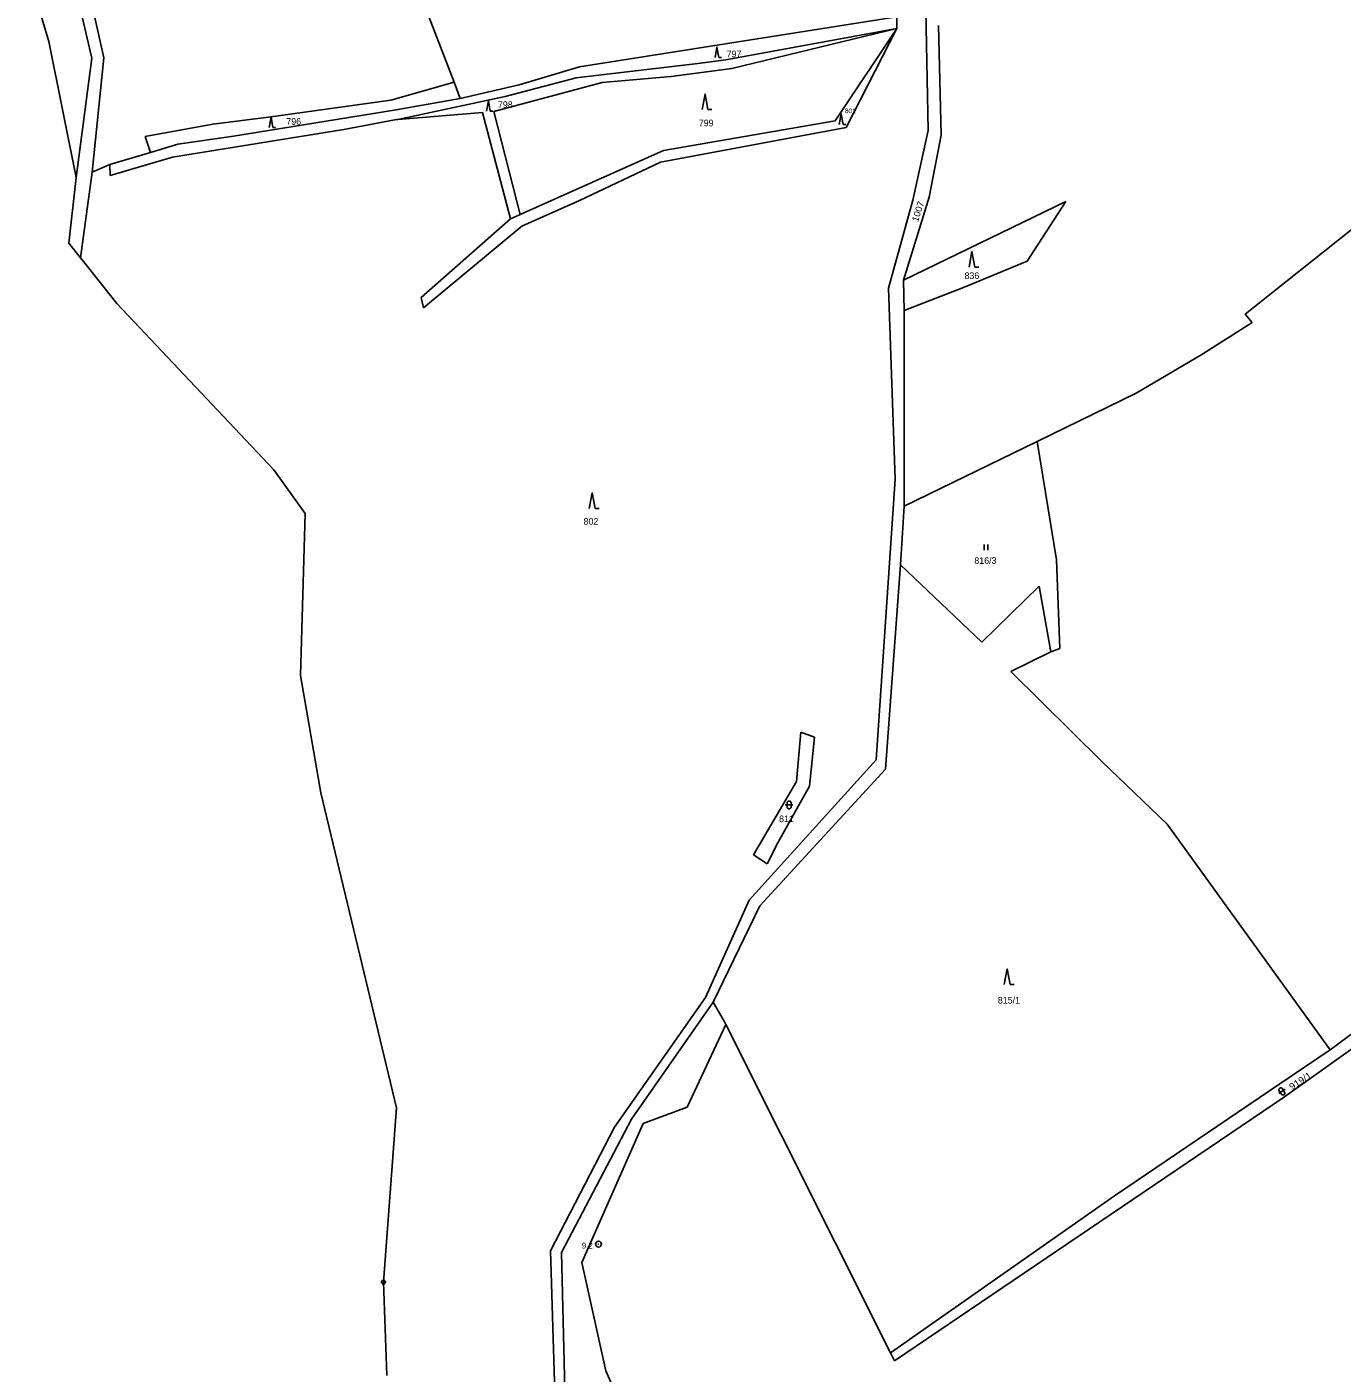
# Model space of a CAD drawing. Extents: x -744132 to -742433, y -984679 to -982287.
# Drawn here: x -744088.1 to -743750.5, y -983360 to -983014.5 of the extents above; entities that cross this region are included whole.
import ezdxf
from ezdxf.enums import TextEntityAlignment as Align

# ---------------------------------------------------------------- set-up
doc = ezdxf.new("R2010")
doc.units = 0
doc.header["$LTSCALE"] = 0.68
for name, color, linetype, lineweight in [('1', 7, 'Continuous', 25), ('3', 7, 'Continuous', 25), ('8', 7, 'Continuous', 25)]:
    doc.layers.add(name, color=color, linetype=linetype, lineweight=lineweight)
doc.layers.add('2', color=7, linetype='Continuous')

msp = doc.modelspace()

# ---------------------------------------------------------------- linework, layer by layer
at = {"layer": '1'}
for p, q in [((-744068.32, -983022.46), (-744075.46, -982990.35)), ((-744071.39, -983022.53), (-744078.73, -982990.95)), ((-744088.07, -982999.56), (-744082.42, -983018.25)), ((-743988.75, -983001.83), (-743978.43, -983028.72)), ((-743856.71, -983041.1), (-743857.33, -983010.2)), ((-743946.2, -983024.79), (-743864.76, -983011.89)), ((-743864.76, -983011.89), (-743864.74, -983014.91)), ((-743854.03, -983014.11), (-743853.38, -983042.28)), ((-743907.08, -983025.18), (-743864.74, -983014.91)), ((-743880.6, -983038.62), (-743864.74, -983014.91)), ((-743877.79, -983040.3), (-743864.74, -983014.91)), ((-744082.42, -983018.25), (-744075.45, -983053.19)), ((-744071.39, -983022.53), (-744075.45, -983053.19)), ((-744068.32, -983022.46), (-744071.3, -983051.79)), ((-743961.67, -983029.4), (-743946.2, -983024.79)), ((-743947.1, -983027.57), (-743915.85, -983023.86)), ((-743965.31, -983032.34), (-743947.1, -983027.57)), ((-743940.43, -983028.79), (-743922.65, -983027.26)), ((-743922.65, -983027.26), (-743907.08, -983025.18)), ((-743994.69, -983033.33), (-743978.43, -983028.72)), ((-743978.43, -983028.72), (-743976.84, -983032.9)), ((-743976.84, -983032.9), (-743961.67, -983029.4)), ((-743940.43, -983028.79), (-743968.2, -983036.18)), ((-744026.05, -983037.66), (-743994.69, -983033.33)), ((-743976.84, -983032.9), (-743993.28, -983035.82)), ((-743992.82, -983038.24), (-743965.31, -983032.34)), ((-744040.33, -983039.5), (-744026.05, -983037.66)), ((-743993.28, -983035.82), (-744035.03, -983042.53)), ((-743993.21, -983038.29), (-744006.69, -983040.82)), ((-743992.82, -983038.24), (-743993.21, -983038.29)), ((-743971.16, -983036.51), (-743992.82, -983038.24)), ((-743963.92, -983063.75), (-743971.16, -983036.51)), ((-743968.2, -983036.18), (-743961.46, -983062.65)), ((-743924.66, -983046.23), (-743880.6, -983038.62)), ((-744057.72, -983042.67), (-744040.33, -983039.5)), ((-744006.69, -983040.82), (-744050.73, -983047.93)), ((-743925.42, -983049.23), (-743877.79, -983040.3)), ((-743860.62, -983058.97), (-743856.71, -983041.1)), ((-743853.38, -983042.28), (-743856.43, -983058.2)), ((-744056.34, -983046.75), (-744057.72, -983042.67)), ((-744049.31, -983044.58), (-744056.34, -983046.75)), ((-744035.03, -983042.53), (-744049.31, -983044.58)), ((-744066.82, -983049.8), (-744056.34, -983046.75)), ((-744050.73, -983047.93), (-744066.7, -983052.68)), ((-743961.46, -983062.65), (-743924.66, -983046.23)), ((-743946.23, -983059.07), (-743925.42, -983049.23)), ((-744071.3, -983051.79), (-744074.3, -983073.78)), ((-744066.82, -983049.8), (-744071.3, -983051.79)), ((-744066.82, -983049.8), (-744066.7, -983052.68)), ((-744075.45, -983053.19), (-744077.28, -983070.03)), ((-743961.03, -983065.64), (-743946.23, -983059.07)), ((-743866.9, -983081.58), (-743860.62, -983058.97)), ((-743856.43, -983058.2), (-743863.07, -983079.53)), ((-743863.07, -983079.53), (-743821.36, -983059.36)), ((-743821.36, -983059.36), (-743831.27, -983074.64)), ((-743963.92, -983063.75), (-743961.46, -983062.65)), ((-743986.86, -983084), (-743963.92, -983063.75)), ((-743986.28, -983086.57), (-743961.03, -983065.64)), ((-743747.4, -983065.95), (-743775.33, -983088.23)), ((-744077.28, -983070.03), (-744074.3, -983073.78)), ((-744074.3, -983073.78), (-744072.89, -983075.56)), ((-744072.89, -983075.56), (-744064.97, -983085.53)), ((-743831.27, -983074.64), (-743847.68, -983081.43)), ((-743862.92, -983087.27), (-743863.07, -983079.53)), ((-743865.2, -983130.57), (-743866.9, -983081.58)), ((-743847.68, -983081.43), (-743862.92, -983087.27)), ((-744064.97, -983085.53), (-744024.7, -983128.17)), ((-743986.86, -983084), (-743986.28, -983086.57)), ((-743862.92, -983087.27), (-743862.86, -983137.53)), ((-743786.49, -983098.57), (-743773.52, -983090.41)), ((-743773.52, -983090.41), (-743775.33, -983088.23)), ((-743803.29, -983108.52), (-743786.49, -983098.57)), ((-743828.77, -983120.93), (-743803.29, -983108.52)), ((-743862.86, -983137.53), (-743828.77, -983120.93)), ((-743823.78, -983151.26), (-743828.77, -983120.93)), ((-744024.7, -983128.17), (-744016.63, -983139.41)), ((-743870.07, -983202.63), (-743865.2, -983130.57)), ((-743862.86, -983137.53), (-743863.8, -983152.55)), ((-744016.63, -983139.41), (-744017.88, -983180.94)), ((-743863.8, -983152.55), (-743867.67, -983205.06)), ((-743863.8, -983152.55), (-743842.94, -983172.39)), ((-743822.92, -983174.05), (-743823.78, -983151.26)), ((-743842.94, -983172.39), (-743828.24, -983158.03)), ((-743828.24, -983158.03), (-743825.25, -983174.92)), ((-743835.53, -983179.96), (-743825.25, -983174.92)), ((-743825.25, -983174.92), (-743822.92, -983174.05)), ((-743812.18, -983203.03), (-743835.53, -983179.96)), ((-744017.88, -983180.94), (-744012.6, -983211.1)), ((-743890.53, -983208.23), (-743889.37, -983195.5)), ((-743889.37, -983195.5), (-743885.92, -983196.78)), ((-743885.92, -983196.78), (-743887.17, -983209.4)), ((-743902.64, -983238.65), (-743870.07, -983202.63)), ((-743795.41, -983219.1), (-743812.18, -983203.03)), ((-743901.59, -983227.05), (-743890.53, -983208.23)), ((-743867.67, -983205.06), (-743899.93, -983240.12)), ((-744012.6, -983211.1), (-743993.19, -983291.95)), ((-743887.17, -983209.4), (-743895.2, -983223.73)), ((-743753.54, -983277.08), (-743795.41, -983219.1)), ((-743895.2, -983223.73), (-743898.03, -983229.33)), ((-743898.03, -983229.33), (-743901.59, -983227.05)), ((-743902.64, -983238.65), (-743913.9, -983263.64)), ((-743899.93, -983240.12), (-743911.88, -983264.84)), ((-743704.56, -983240.84), (-743753.54, -983277.08)), ((-743913.9, -983263.64), (-743937.21, -983296.92)), ((-743911.88, -983264.84), (-743932.88, -983294.87)), ((-743911.88, -983264.84), (-743908.97, -983269.89)), ((-743765.21, -983289.16), (-743733.29, -983266.29)), ((-743908.97, -983269.89), (-743908.62, -983270.58)), ((-743908.62, -983270.58), (-743918.59, -983291.77)), ((-743908.62, -983270.58), (-743866.41, -983354.8)), ((-743766.49, -983285.81), (-743753.54, -983277.08)), ((-743808.87, -983314.53), (-743766.49, -983285.81)), ((-743865.37, -983356.9), (-743765.21, -983289.16)), ((-743993.19, -983291.95), (-743996.56, -983336.67)), ((-743918.59, -983291.77), (-743929.92, -983295.93)), ((-743937.21, -983296.92), (-743953.68, -983328.65)), ((-743932.88, -983294.87), (-743950.83, -983329.06)), ((-743929.92, -983295.93), (-743945.63, -983331.63)), ((-743866.41, -983354.8), (-743808.87, -983314.53)), ((-743953.68, -983328.65), (-743951.88, -983384.93)), ((-743950.83, -983329.06), (-743948.3, -983432.7)), ((-743945.63, -983331.63), (-743939.5, -983359.44)), ((-743996.56, -983336.67), (-743995.72, -983360.62)), ((-743866.41, -983354.8), (-743865.37, -983356.9)), ((-743939.5, -983359.44), (-743926.31, -983389.16))]:
    msp.add_line(p, q, dxfattribs=at)
msp.add_lwpolyline([(-743915.85, -983023.86), (-743908.66, -983022.98), (-743864.74, -983014.91)], dxfattribs=at)
at = {"layer": '3'}
for p, q in [((-743910.428, -983022.37), (-743909.76, -983022.37)), ((-743969.118, -983036.13), (-743968.45, -983036.13)), ((-743913.25, -983035.74), (-743912.254, -983035.74)), ((-744024.908, -983040.36), (-744024.24, -983040.36)), ((-743878.538, -983039.58), (-743877.87, -983039.58)), ((-743844.73, -983076.15), (-743843.734, -983076.15)), ((-743942.21, -983138.13), (-743941.214, -983138.13)), ((-743842.381, -983148.83), (-743842.381, -983147.33)), ((-743841.38, -983148.83), (-743841.38, -983147.33)), ((-743893.431, -983214.211), (-743891.429, -983214.211)), ((-743892.931, -983213.711), (-743892.931, -983214.712)), ((-743891.929, -983214.712), (-743891.929, -983213.711)), ((-743835.67, -983260.3), (-743834.674, -983260.3)), ((-743766.744, -983288.288), (-743765.064, -983287.197)), ((-743766.596, -983287.595), (-743766.051, -983288.435)), ((-743765.212, -983287.889), (-743765.757, -983287.05))]:
    msp.add_line(p, q, dxfattribs=at)
for points in [[(-743910.428, -983022.37), (-743910.93, -983019.69), (-743911.432, -983022.37)], [(-743913.25, -983035.74), (-743914, -983031.74), (-743914.75, -983035.74)], [(-743969.118, -983036.13), (-743969.62, -983033.45), (-743970.122, -983036.13)], [(-744024.908, -983040.36), (-744025.41, -983037.68), (-744025.912, -983040.36)], [(-743878.538, -983039.58), (-743879.04, -983036.9), (-743879.542, -983039.58)], [(-743844.73, -983076.15), (-743845.48, -983072.15), (-743846.23, -983076.15)], [(-743942.21, -983138.13), (-743942.96, -983134.13), (-743943.71, -983138.13)], [(-743835.67, -983260.3), (-743836.42, -983256.3), (-743837.17, -983260.3)]]:
    msp.add_lwpolyline(points, dxfattribs=at)
for centre, start, end in [((-743892.43, -983213.7109), 0, 180), ((-743892.43, -983214.7109), 180, 359.98789), ((-743766.1765, -983287.3227), 33, 213), ((-743765.6318, -983288.1614), 213, 32.98789)]:
    msp.add_arc(centre, 0.5, start, end, dxfattribs=at)
at = {"layer": '8'}
for centre, radius in [((-743941.33, -983326.9398), 0.75), ((-743941.33, -983326.9398), 0.03), ((-743996.56, -983336.6699), 0.5), ((-743996.56, -983336.6699), 0.0303)]:
    msp.add_circle(centre, radius, dxfattribs=at)

# ---------------------------------------------------------------- texts
at = {"layer": '2'}
for s, height, p in [('797', 1.7, (-743908.46, -983022.315)), ('798', 1.7, (-743967.16, -983035.315)), ('801', 1.19, (-743878.08, -983036.647)), ('796', 1.7, (-744021.48, -983039.625)), ('799', 1.7, (-743915.6, -983040.015)), ('836', 1.7, (-743847.39, -983079.225)), ('802', 1.7, (-743945.19, -983142.275)), ('816/3', 1.7, (-743844.87, -983152.325)), ('811', 1.7, (-743894.99, -983218.625)), ('815/1', 1.7, (-743838.84, -983265.185))]:
    msp.add_text(s, height=height, dxfattribs=at).set_placement(p)
for s, rotation, width, p in [('1007', 72, 1.05, (-743859.345, -983064.671)), ('919/1', 33, 1.1, (-743763.358, -983287.466))]:
    msp.add_text(s, height=1.7, rotation=rotation, dxfattribs=dict(at, width=width)).set_placement(p)
at = {"layer": '8'}
msp.add_text('9.2', height=1.5, dxfattribs=at).set_placement((-743942.83, -983328.057), align=Align.RIGHT)

doc.saveas('drawing.dxf')
